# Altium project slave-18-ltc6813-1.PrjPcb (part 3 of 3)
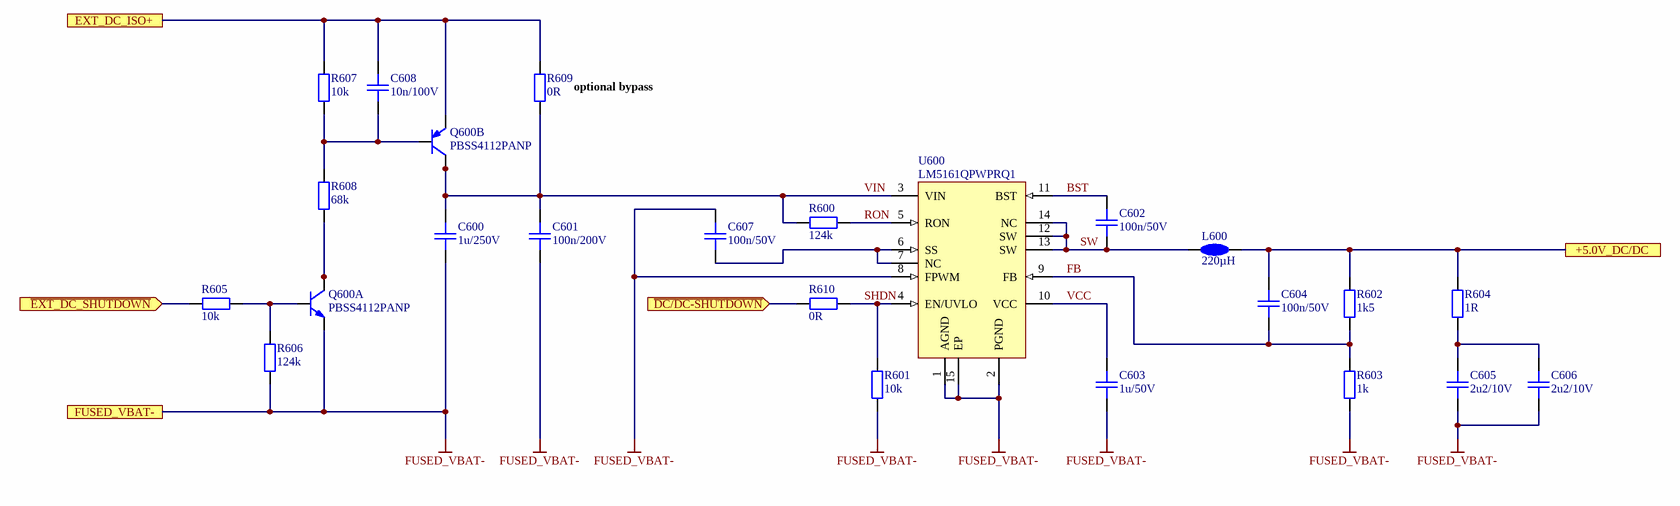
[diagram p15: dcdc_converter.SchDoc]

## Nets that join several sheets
+3.0V_VREF2: connectors (C401.2 C405.2 X400.17 X404.1), U_primary_LTC (C1402_1.2 IC1400_1.50 TP1402_1.1), U_primary_analog_in (9 pins)
+3.0V_VREF2: connectors (C400.2 C406.2 X401.17 X404.2), U_secondary_analog_in (9 pins), U_secondary_LTC (C1402_2.2 IC1400_2.50 TP1402_2.1)
+5.0V_VREG: connectors (C402.2 C404.2 X402.9 X404.3), feedback (D1100.2), U_primary_LTC (16 pins), U_primary_dcdc_converter (C604_1.2 L600_1.2 R602_1.1 R604_1.1), U_primary_digital_io (13 pins), U_primary_eeprom_temp_sens (6 pins), U_primary_analog_in (15 pins)
+5.0V_VREG: connectors (C403.2 C407.2 X403.9 X404.4), feedback (D1100.1), U_secondary_digital_io (13 pins), U_secondary_eeprom_temp_sens (6 pins), U_secondary_analog_in (15 pins), U_secondary_dcdc_converter (C604_2.2 L600_2.2 R602_2.1 R604_2.1), U_secondary_LTC (16 pins)
FUSED_VBAT+: cell_fuses (F300.2), U_primary_LTC (D1400_1.1), U_secondary_LTC (D1400_2.1)
FUSED_VBAT-: cell_fuses (F320.2), U_primary_input_filter (18 pins), U_secondary_input_filter (18 pins), ext_supply (6 pins), connectors (14 pins), feedback (C1100.1 R1118.2), U_primary_LTC (14 pins), U_secondary_digital_io (C700_1.1 C701_1.1 U700_1.2 U700_1.8), U_secondary_eeprom_temp_sens (5 pins), U_secondary_analog_in (25 pins), bat_connectors (16 pins), U_primary_dcdc_converter (14 pins), U_secondary_dcdc_converter (14 pins), U_secondary_LTC (14 pins), U_primary_digital_io (C700_2.1 C701_2.1 U700_2.2 U700_2.8), U_primary_eeprom_temp_sens (5 pins), U_primary_analog_in (25 pins)
VBAT+: cell_fuses (F300.1 SJ300.1), bat_connectors (X200.11)
VBAT-: cell_fuses (F320.1 SJ301.2), bat_connectors (X200.1)
CELL_0+: cell_fuses (F318.1), bat_connectors (X200.2)
CELL_0-: cell_fuses (F319.1 SJ301.1), bat_connectors (X200.13)
CELL_1+: cell_fuses (F317.1), bat_connectors (X200.14)
CELL_2+: cell_fuses (F316.1), bat_connectors (X200.3)
CELL_3+: cell_fuses (F315.1), bat_connectors (X200.15)
CELL_4+: cell_fuses (F314.1), bat_connectors (X200.4)
CELL_5+: cell_fuses (F313.1), bat_connectors (X200.16)
CELL_6+: cell_fuses (F312.1), bat_connectors (X200.5)
CELL_7+: cell_fuses (F311.1), bat_connectors (X200.17)
CELL_8+: cell_fuses (F310.1), bat_connectors (X200.6)
CELL_9+: cell_fuses (F309.1), bat_connectors (X200.18)
CELL_10+: cell_fuses (F308.1), bat_connectors (X200.7)
CELL_11+: cell_fuses (F307.1), bat_connectors (X200.19)
CELL_12+: cell_fuses (F306.1), bat_connectors (X200.8)
CELL_13+: cell_fuses (F305.1), bat_connectors (X200.20)
CELL_14+: cell_fuses (F304.1), bat_connectors (X200.9)
CELL_15+: cell_fuses (F303.1), bat_connectors (X200.21)
CELL_16+: cell_fuses (F302.1), bat_connectors (X200.10)
CELL_17+: cell_fuses (F301.1 SJ300.2), bat_connectors (X200.22)
CELL_FEEDBACK.CELL0_FEEDBACK+: feedback (R1105.1), passive_balancing (R1505.2 R1511.2 T1505.3)
CELL_FEEDBACK.CELL1_FEEDBACK+: feedback (R1104.1), passive_balancing (R1504.2 R1510.2 T1504.3)
CELL_FEEDBACK.CELL2_FEEDBACK+: feedback (R1103.1), passive_balancing (R1503.2 R1509.2 T1503.3)
CELL_FEEDBACK.CELL3_FEEDBACK+: feedback (R1102.1), passive_balancing (R1502.2 R1508.2 T1502.3)
CELL_FEEDBACK.CELL4_FEEDBACK+: feedback (R1101.1), passive_balancing (R1501.2 R1507.2 T1501.3)
CELL_FEEDBACK.CELL5_FEEDBACK+: feedback (R1100.1), passive_balancing (R1500.2 R1506.2 T1500.3)
CELL_FEEDBACK.CELL6_FEEDBACK+: feedback (R1111.1), passive_balancing (R1523.2 R1529.2 T1511.3)
CELL_FEEDBACK.CELL7_FEEDBACK+: feedback (R1110.1), passive_balancing (R1522.2 R1528.2 T1510.3)
CELL_FEEDBACK.CELL8_FEEDBACK+: feedback (R1109.1), passive_balancing (R1521.2 R1527.2 T1509.3)
CELL_FEEDBACK.CELL9_FEEDBACK+: feedback (R1108.1), passive_balancing (R1520.2 R1526.2 T1508.3)
CELL_FEEDBACK.CELL10_FEEDBACK+: feedback (R1107.1), passive_balancing (R1519.2 R1525.2 T1507.3)
CELL_FEEDBACK.CELL11_FEEDBACK+: feedback (R1106.1), passive_balancing (R1518.2 R1524.2 T1506.3)
CELL_FEEDBACK.CELL12_FEEDBACK+: feedback (R1117.1), passive_balancing (R1541.2 R1547.2 T1517.3)
CELL_FEEDBACK.CELL13_FEEDBACK+: feedback (R1116.1), passive_balancing (R1540.2 R1546.2 T1516.3)
CELL_FEEDBACK.CELL14_FEEDBACK+: feedback (R1115.1), passive_balancing (R1539.2 R1545.2 T1515.3)
CELL_FEEDBACK.CELL15_FEEDBACK+: feedback (R1114.1), passive_balancing (R1538.2 R1544.2 T1514.3)
CELL_FEEDBACK.CELL16_FEEDBACK+: feedback (R1113.1), passive_balancing (R1537.2 R1543.2 T1513.3)
CELL_FEEDBACK.CELL17_FEEDBACK+: feedback (R1112.1), passive_balancing (R1536.2 R1542.2 T1512.3)
EXT_DC_IN+: ext_supply (F900.1), ext_supply_con (X1000.1 X1000.3 X1001.1 X1002.1)
EXT_DC_IN-: ext_supply (10 pins), ext_supply_con (X1000.2 X1000.4 X1001.2 X1002.2)
EXT_DC_ISO+: ext_supply (5 pins), U_primary_LTC (D1400_1.2 D1401_1.1 R1401_1.1), U_primary_dcdc_converter (C608_1.1 Q600_1.4 R607_1.2 R609_1.2), U_secondary_dcdc_converter (C608_2.1 Q600_2.4 R607_2.2 R609_2.2), U_secondary_LTC (D1400_2.2 D1401_2.1 R1401_2.1)
FUSED_CELL.CELL_0+: cell_fuses (F318.2), U_primary_input_filter (R1305_1.1), U_secondary_input_filter (R1305_2.1), feedback (U1104.2), passive_balancing (R1504.1 R1510.1 T1505.2)
FUSED_CELL.CELL_0-: cell_fuses (F319.2), U_primary_input_filter (R1306_1.1), U_secondary_input_filter (R1306_2.1), feedback (U1105.2), passive_balancing (R1505.1 R1511.1)
FUSED_CELL.CELL_1+: cell_fuses (F317.2), U_primary_input_filter (R1304_1.1), U_secondary_input_filter (R1304_2.1), feedback (U1103.2), passive_balancing (R1503.1 R1509.1 T1504.2)
FUSED_CELL.CELL_2+: cell_fuses (F316.2), U_primary_input_filter (R1303_1.1), U_secondary_input_filter (R1303_2.1), feedback (U1102.2), passive_balancing (R1502.1 R1508.1 T1503.2)
FUSED_CELL.CELL_3+: cell_fuses (F315.2), U_primary_input_filter (R1302_1.1), U_secondary_input_filter (R1302_2.1), feedback (U1101.2), passive_balancing (R1501.1 R1507.1 T1502.2)
FUSED_CELL.CELL_4+: cell_fuses (F314.2), U_primary_input_filter (R1301_1.1), U_secondary_input_filter (R1301_2.1), feedback (U1100.2), passive_balancing (R1500.1 R1506.1 T1501.2)
FUSED_CELL.CELL_5+: cell_fuses (F313.2), U_primary_input_filter (R1300_1.1), U_secondary_input_filter (R1300_2.1), feedback (U1111.2), passive_balancing (R1523.1 R1529.1 T1500.2)
FUSED_CELL.CELL_6+: cell_fuses (F312.2), U_primary_input_filter (R1312_1.1), U_secondary_input_filter (R1312_2.1), feedback (U1110.2), passive_balancing (R1522.1 R1528.1 T1511.2)
FUSED_CELL.CELL_7+: cell_fuses (F311.2), U_primary_input_filter (R1311_1.1), U_secondary_input_filter (R1311_2.1), feedback (U1109.2), passive_balancing (R1521.1 R1527.1 T1510.2)
FUSED_CELL.CELL_8+: cell_fuses (F310.2), U_primary_input_filter (R1310_1.1), U_secondary_input_filter (R1310_2.1), feedback (U1108.2), passive_balancing (R1520.1 R1526.1 T1509.2)
FUSED_CELL.CELL_9+: cell_fuses (F309.2), U_primary_input_filter (R1309_1.1), U_secondary_input_filter (R1309_2.1), feedback (U1107.2), passive_balancing (R1519.1 R1525.1 T1508.2)
FUSED_CELL.CELL_10+: cell_fuses (F308.2), U_primary_input_filter (R1308_1.1), U_secondary_input_filter (R1308_2.1), feedback (U1106.2), passive_balancing (R1518.1 R1524.1 T1507.2)
FUSED_CELL.CELL_11+: cell_fuses (F307.2), U_primary_input_filter (R1307_1.1), U_secondary_input_filter (R1307_2.1), feedback (U1117.2), passive_balancing (R1541.1 R1547.1 T1506.2)
FUSED_CELL.CELL_12+: cell_fuses (F306.2), U_primary_input_filter (R1318_1.1), U_secondary_input_filter (R1318_2.1), feedback (U1116.2), passive_balancing (R1540.1 R1546.1 T1517.2)
FUSED_CELL.CELL_13+: cell_fuses (F305.2), U_primary_input_filter (R1317_1.1), U_secondary_input_filter (R1317_2.1), feedback (U1115.2), passive_balancing (R1539.1 R1545.1 T1516.2)
FUSED_CELL.CELL_14+: cell_fuses (F304.2), U_primary_input_filter (R1316_1.1), U_secondary_input_filter (R1316_2.1), feedback (U1114.2), passive_balancing (R1538.1 R1544.1 T1515.2)
FUSED_CELL.CELL_15+: cell_fuses (F303.2), U_primary_input_filter (R1315_1.1), U_secondary_input_filter (R1315_2.1), feedback (U1113.2), passive_balancing (R1537.1 R1543.1 T1514.2)
FUSED_CELL.CELL_16+: cell_fuses (F302.2), U_primary_input_filter (R1314_1.1), U_secondary_input_filter (R1314_2.1), feedback (U1112.2), passive_balancing (R1536.1 R1542.1 T1513.2)
FUSED_CELL.CELL_17+: cell_fuses (F301.2), U_primary_input_filter (R1313_1.1), U_secondary_input_filter (R1313_2.1), passive_balancing (T1512.2)
GLOBAL-BAL-FB: feedback (20 pins), U_primary_LTC (R1413_1.1), U_secondary_LTC (R1413_2.1)
PRIMARY-ANALOG-IN_0: connectors (X400.1), U_primary_analog_in (IC104_2.4)
PRIMARY-ANALOG-IN_1: connectors (X400.2), U_primary_analog_in (IC104_2.5)
PRIMARY-ANALOG-IN_2: connectors (X400.3), U_primary_analog_in (IC104_2.6)
PRIMARY-ANALOG-IN_3: connectors (X400.4), U_primary_analog_in (IC104_2.7)
PRIMARY-ANALOG-IN_4: connectors (X400.5), U_primary_analog_in (IC104_2.12)
PRIMARY-ANALOG-IN_5: connectors (X400.6), U_primary_analog_in (IC104_2.11)
PRIMARY-ANALOG-IN_6: connectors (X400.7), U_primary_analog_in (IC104_2.10)
PRIMARY-ANALOG-IN_7: connectors (X400.8), U_primary_analog_in (IC104_2.9)
PRIMARY-ANALOG-IN_8: connectors (X400.9), U_primary_analog_in (IC101_2.4)
PRIMARY-ANALOG-IN_9: connectors (X400.10), U_primary_analog_in (IC101_2.5)
PRIMARY-ANALOG-IN_10: connectors (X400.11), U_primary_analog_in (IC101_2.6)
PRIMARY-ANALOG-IN_11: connectors (X400.12), U_primary_analog_in (IC101_2.7)
PRIMARY-ANALOG-IN_12: connectors (X400.13), U_primary_analog_in (IC101_2.12)
PRIMARY-ANALOG-IN_13: connectors (X400.14), U_primary_analog_in (IC101_2.11)
PRIMARY-ANALOG-IN_14: connectors (X400.15), U_primary_analog_in (IC101_2.10)
PRIMARY-ANALOG-IN_15: connectors (X400.16), U_primary_analog_in (IC101_2.9)
PRIMARY-C0: U_primary_input_filter (C1311_1.2 R1306_1.2 Z1305_1.2), U_primary_LTC (IC1400_1.38)
PRIMARY-C1: U_primary_input_filter (6 pins), U_primary_LTC (IC1400_1.36)
PRIMARY-C2: U_primary_input_filter (6 pins), U_primary_LTC (IC1400_1.34)
PRIMARY-C3: U_primary_input_filter (6 pins), U_primary_LTC (IC1400_1.32)
PRIMARY-C4: U_primary_input_filter (6 pins), U_primary_LTC (IC1400_1.30)
PRIMARY-C5: U_primary_input_filter (6 pins), U_primary_LTC (IC1400_1.28)
PRIMARY-C6: U_primary_input_filter (6 pins), U_primary_LTC (IC1400_1.26)
PRIMARY-C7: U_primary_input_filter (6 pins), U_primary_LTC (IC1400_1.24)
PRIMARY-C8: U_primary_input_filter (6 pins), U_primary_LTC (IC1400_1.22)
PRIMARY-C9: U_primary_input_filter (6 pins), U_primary_LTC (IC1400_1.20)
PRIMARY-C10: U_primary_input_filter (6 pins), U_primary_LTC (IC1400_1.18)
PRIMARY-C11: U_primary_input_filter (6 pins), U_primary_LTC (IC1400_1.16)
PRIMARY-C12: U_primary_input_filter (6 pins), U_primary_LTC (IC1400_1.14)
PRIMARY-C13: U_primary_input_filter (6 pins), U_primary_LTC (IC1400_1.12)
PRIMARY-C14: U_primary_input_filter (6 pins), U_primary_LTC (IC1400_1.10)
PRIMARY-C15: U_primary_input_filter (6 pins), U_primary_LTC (IC1400_1.8)
PRIMARY-C16: U_primary_input_filter (6 pins), U_primary_LTC (IC1400_1.6)
PRIMARY-C17: U_primary_input_filter (6 pins), U_primary_LTC (IC1400_1.4)
PRIMARY-C18: U_primary_input_filter (C1324_1.1 C1330_1.1 R1313_1.2 Z1312_1.1), U_primary_LTC (IC1400_1.2)
PRIMARY-DIGITAL-IO_0: connectors (X402.1), U_primary_digital_io (R700_2.1 U700_2.4)
PRIMARY-DIGITAL-IO_1: connectors (X402.2), U_primary_digital_io (R701_2.1 U700_2.5)
PRIMARY-DIGITAL-IO_2: connectors (X402.3), U_primary_digital_io (R702_2.1 U700_2.6)
PRIMARY-DIGITAL-IO_3: connectors (X402.4), U_primary_digital_io (R703_2.1 U700_2.7)
PRIMARY-DIGITAL-IO_4: connectors (X402.5), U_primary_digital_io (R704_2.1 U700_2.9)
PRIMARY-DIGITAL-IO_5: connectors (X402.6), U_primary_digital_io (R705_2.1 U700_2.10)
PRIMARY-DIGITAL-IO_6: connectors (X402.7), U_primary_digital_io (R706_2.1 U700_2.11)
PRIMARY-DIGITAL-IO_7: connectors (X402.8), U_primary_digital_io (R707_2.1 U700_2.12)
PRIMARY-GPIO1-OPT: connectors (X404.5), U_primary_LTC (R1408_1.1 R1425_1.1)
PRIMARY-GPIO2-OPT: connectors (X404.7), U_primary_LTC (R1410_1.1 R1426_1.1)
PRIMARY-GPIO3-OPT: connectors (X404.9), U_primary_LTC (R1412_1.1 R1427_1.1)
PRIMARY-GPIO4-OPT: connectors (X404.11), U_primary_LTC (R1414_1.1)
PRIMARY-GPIO5-OPT: connectors (X404.13), U_primary_LTC (R1416_1.1)
PRIMARY-GPIO6: connectors (X405.1), U_primary_LTC (IC1400_1.44 R1421_1.1)
PRIMARY-GPIO7: connectors (X405.3), U_primary_LTC (IC1400_1.45 R1422_1.1)
PRIMARY-GPIO8: connectors (X405.5), U_primary_LTC (IC1400_1.46 R1423_1.1)
PRIMARY-GPIO9: connectors (X405.7), U_primary_LTC (IC1400_1.47 R1424_1.1)
PRIMARY-IN+: U_primary_LTC (TP1405_1.1 TR1400_1.4), daisy_chain_connectors (X500.1)
PRIMARY-IN-: U_primary_LTC (TP1404_1.1 TR1400_1.6), daisy_chain_connectors (X500.2)
PRIMARY-LTC-DRIVE: U_primary_LTC (IC1400_1.49), U_primary_dcdc_converter (R605_1.1 R610_1.2)
PRIMARY-MUX-DATA_TEMP: U_primary_LTC (R1409_1.1), U_primary_analog_in (C106_2.2 R108_2.2)
PRIMARY-MUX-DATA_USER: U_primary_LTC (R1411_1.1), U_primary_analog_in (C107_2.2 R109_2.2)
PRIMARY-OUT+: U_primary_LTC (TP1406_1.1 TR1400_1.1), daisy_chain_connectors (X501.1)
PRIMARY-OUT-: U_primary_LTC (TP1407_1.1 TR1400_1.3), daisy_chain_connectors (X501.2)
PRIMARY-S1: passive_balancing (R1517.2), U_primary_LTC (IC1400_1.37)
PRIMARY-S2: passive_balancing (R1516.2), U_primary_LTC (IC1400_1.35)
PRIMARY-S3: passive_balancing (R1515.2), U_primary_LTC (IC1400_1.33)
PRIMARY-S4: passive_balancing (R1514.2), U_primary_LTC (IC1400_1.31)
PRIMARY-S5: passive_balancing (R1513.2), U_primary_LTC (IC1400_1.29)
PRIMARY-S6: passive_balancing (R1512.2), U_primary_LTC (IC1400_1.27)
PRIMARY-S7: passive_balancing (R1535.2), U_primary_LTC (IC1400_1.25)
PRIMARY-S8: passive_balancing (R1534.2), U_primary_LTC (IC1400_1.23)
PRIMARY-S9: passive_balancing (R1533.2), U_primary_LTC (IC1400_1.21)
PRIMARY-S10: passive_balancing (R1532.2), U_primary_LTC (IC1400_1.19)
PRIMARY-S11: passive_balancing (R1531.2), U_primary_LTC (IC1400_1.17)
PRIMARY-S12: passive_balancing (R1530.2), U_primary_LTC (IC1400_1.15)
PRIMARY-S13: passive_balancing (R1553.2), U_primary_LTC (IC1400_1.13)
PRIMARY-S14: passive_balancing (R1552.2), U_primary_LTC (IC1400_1.11)
PRIMARY-S15: passive_balancing (R1551.2), U_primary_LTC (IC1400_1.9)
PRIMARY-S16: passive_balancing (R1550.2), U_primary_LTC (IC1400_1.7)
PRIMARY-S17: passive_balancing (R1549.2), U_primary_LTC (IC1400_1.5)
PRIMARY-S18: passive_balancing (R1548.2), U_primary_LTC (IC1400_1.3)
PRIMARY-SCL: U_primary_LTC (R1417_1.1 R1420_1.1 TP1409_1.1), U_primary_digital_io (U700_2.14), U_primary_eeprom_temp_sens (IC800_2.4 IC801_2.6), U_primary_analog_in (IC100_2.1 IC101_2.1 IC104_2.1)
PRIMARY-SDA: U_primary_LTC (R1415_1.1 R1419_1.1 TP1408_1.1), U_primary_digital_io (U700_2.15), U_primary_eeprom_temp_sens (IC800_2.5 IC801_2.5), U_primary_analog_in (IC100_2.3 IC101_2.3 IC104_2.3)
PRIMARY-T-SENSOR_0: bat_connectors (X201.1), U_primary_analog_in (R107_2.1 R112_2.2)
PRIMARY-T-SENSOR_1: bat_connectors (X201.2), U_primary_analog_in (R106_2.1 R113_2.2)
PRIMARY-T-SENSOR_2: bat_connectors (X201.3), U_primary_analog_in (R105_2.1 R114_2.2)
PRIMARY-T-SENSOR_3: bat_connectors (X201.4), U_primary_analog_in (R104_2.1 R115_2.2)
PRIMARY-T-SENSOR_4: bat_connectors (X201.5), U_primary_analog_in (R103_2.1 R116_2.2)
PRIMARY-T-SENSOR_5: bat_connectors (X201.6), U_primary_analog_in (R102_2.1 R117_2.2)
PRIMARY-T-SENSOR_6: bat_connectors (X201.7), U_primary_analog_in (R101_2.1 R118_2.2)
PRIMARY-T-SENSOR_7: bat_connectors (X201.8), U_primary_analog_in (R100_2.1 R119_2.2)
PRIMARY-TEMP-ALERT: connectors (X404.17), U_primary_eeprom_temp_sens (IC800_2.3 R800_2.1)
PRIMARY-WDT: connectors (X404.15), U_primary_LTC (IC1400_1.56 R1404_1.1)
SECONDARY-ANALOG-IN_0: connectors (X401.1), U_secondary_analog_in (IC104_1.4)
SECONDARY-ANALOG-IN_1: connectors (X401.2), U_secondary_analog_in (IC104_1.5)
SECONDARY-ANALOG-IN_2: connectors (X401.3), U_secondary_analog_in (IC104_1.6)
SECONDARY-ANALOG-IN_3: connectors (X401.4), U_secondary_analog_in (IC104_1.7)
SECONDARY-ANALOG-IN_4: connectors (X401.5), U_secondary_analog_in (IC104_1.12)
SECONDARY-ANALOG-IN_5: connectors (X401.6), U_secondary_analog_in (IC104_1.11)
SECONDARY-ANALOG-IN_6: connectors (X401.7), U_secondary_analog_in (IC104_1.10)
SECONDARY-ANALOG-IN_7: connectors (X401.8), U_secondary_analog_in (IC104_1.9)
SECONDARY-ANALOG-IN_8: connectors (X401.9), U_secondary_analog_in (IC101_1.4)
SECONDARY-ANALOG-IN_9: connectors (X401.10), U_secondary_analog_in (IC101_1.5)
SECONDARY-ANALOG-IN_10: connectors (X401.11), U_secondary_analog_in (IC101_1.6)
SECONDARY-ANALOG-IN_11: connectors (X401.12), U_secondary_analog_in (IC101_1.7)
SECONDARY-ANALOG-IN_12: connectors (X401.13), U_secondary_analog_in (IC101_1.12)
SECONDARY-ANALOG-IN_13: connectors (X401.14), U_secondary_analog_in (IC101_1.11)
SECONDARY-ANALOG-IN_14: connectors (X401.15), U_secondary_analog_in (IC101_1.10)
SECONDARY-ANALOG-IN_15: connectors (X401.16), U_secondary_analog_in (IC101_1.9)
SECONDARY-C0: U_secondary_input_filter (C1311_2.2 R1306_2.2 Z1305_2.2), U_secondary_LTC (IC1400_2.38)
SECONDARY-C1: U_secondary_input_filter (6 pins), U_secondary_LTC (IC1400_2.36)
SECONDARY-C2: U_secondary_input_filter (6 pins), U_secondary_LTC (IC1400_2.34)
SECONDARY-C3: U_secondary_input_filter (6 pins), U_secondary_LTC (IC1400_2.32)
SECONDARY-C4: U_secondary_input_filter (6 pins), U_secondary_LTC (IC1400_2.30)
SECONDARY-C5: U_secondary_input_filter (6 pins), U_secondary_LTC (IC1400_2.28)
SECONDARY-C6: U_secondary_input_filter (6 pins), U_secondary_LTC (IC1400_2.26)
SECONDARY-C7: U_secondary_input_filter (6 pins), U_secondary_LTC (IC1400_2.24)
SECONDARY-C8: U_secondary_input_filter (6 pins), U_secondary_LTC (IC1400_2.22)
SECONDARY-C9: U_secondary_input_filter (6 pins), U_secondary_LTC (IC1400_2.20)
SECONDARY-C10: U_secondary_input_filter (6 pins), U_secondary_LTC (IC1400_2.18)
SECONDARY-C11: U_secondary_input_filter (6 pins), U_secondary_LTC (IC1400_2.16)
SECONDARY-C12: U_secondary_input_filter (6 pins), U_secondary_LTC (IC1400_2.14)
SECONDARY-C13: U_secondary_input_filter (6 pins), U_secondary_LTC (IC1400_2.12)
SECONDARY-C14: U_secondary_input_filter (6 pins), U_secondary_LTC (IC1400_2.10)
SECONDARY-C15: U_secondary_input_filter (6 pins), U_secondary_LTC (IC1400_2.8)
SECONDARY-C16: U_secondary_input_filter (6 pins), U_secondary_LTC (IC1400_2.6)
SECONDARY-C17: U_secondary_input_filter (6 pins), U_secondary_LTC (IC1400_2.4)
SECONDARY-C18: U_secondary_input_filter (C1324_2.1 C1330_2.1 R1313_2.2 Z1312_2.1), U_secondary_LTC (IC1400_2.2)
SECONDARY-DIGITAL-IO_0: connectors (X403.1), U_secondary_digital_io (R700_1.1 U700_1.4)
SECONDARY-DIGITAL-IO_1: connectors (X403.2), U_secondary_digital_io (R701_1.1 U700_1.5)
SECONDARY-DIGITAL-IO_2: connectors (X403.3), U_secondary_digital_io (R702_1.1 U700_1.6)
SECONDARY-DIGITAL-IO_3: connectors (X403.4), U_secondary_digital_io (R703_1.1 U700_1.7)
SECONDARY-DIGITAL-IO_4: connectors (X403.5), U_secondary_digital_io (R704_1.1 U700_1.9)
SECONDARY-DIGITAL-IO_5: connectors (X403.6), U_secondary_digital_io (R705_1.1 U700_1.10)
SECONDARY-DIGITAL-IO_6: connectors (X403.7), U_secondary_digital_io (R706_1.1 U700_1.11)
SECONDARY-DIGITAL-IO_7: connectors (X403.8), U_secondary_digital_io (R707_1.1 U700_1.12)
SECONDARY-GPIO1-OPT: connectors (X404.6), U_secondary_LTC (R1408_2.1 R1425_2.1)
SECONDARY-GPIO2-OPT: connectors (X404.8), U_secondary_LTC (R1410_2.1 R1426_2.1)
SECONDARY-GPIO3-OPT: connectors (X404.10), U_secondary_LTC (R1412_2.1 R1427_2.1)
SECONDARY-GPIO4-OPT: connectors (X404.12), U_secondary_LTC (R1414_2.1)
SECONDARY-GPIO5-OPT: connectors (X404.14), U_secondary_LTC (R1416_2.1)
SECONDARY-GPIO6: connectors (X405.2), U_secondary_LTC (IC1400_2.44 R1421_2.1)
SECONDARY-GPIO7: connectors (X405.4), U_secondary_LTC (IC1400_2.45 R1422_2.1)
SECONDARY-GPIO8: connectors (X405.6), U_secondary_LTC (IC1400_2.46 R1423_2.1)
SECONDARY-GPIO9: connectors (X405.8), U_secondary_LTC (IC1400_2.47 R1424_2.1)
SECONDARY-IN+: daisy_chain_connectors (X502.1), U_secondary_LTC (TP1405_2.1 TR1400_2.4)
SECONDARY-IN-: daisy_chain_connectors (X502.2), U_secondary_LTC (TP1404_2.1 TR1400_2.6)
SECONDARY-LTC-DRIVE: U_secondary_dcdc_converter (R605_2.1 R610_2.2), U_secondary_LTC (IC1400_2.49)
SECONDARY-MUX-DATA_TEMP: U_secondary_analog_in (C106_1.2 R108_1.2), U_secondary_LTC (R1409_2.1)
SECONDARY-MUX-DATA_USER: U_secondary_analog_in (C107_1.2 R109_1.2), U_secondary_LTC (R1411_2.1)
SECONDARY-OUT+: daisy_chain_connectors (X503.1), U_secondary_LTC (TP1406_2.1 TR1400_2.1)
SECONDARY-OUT-: daisy_chain_connectors (X503.2), U_secondary_LTC (TP1407_2.1 TR1400_2.3)
SECONDARY-SCL: U_secondary_digital_io (U700_1.14), U_secondary_eeprom_temp_sens (IC800_1.4 IC801_1.6), U_secondary_analog_in (IC100_1.1 IC101_1.1 IC104_1.1), U_secondary_LTC (R1417_2.1 R1420_2.1 TP1409_2.1)
SECONDARY-SDA: U_secondary_digital_io (U700_1.15), U_secondary_eeprom_temp_sens (IC800_1.5 IC801_1.5), U_secondary_analog_in (IC100_1.3 IC101_1.3 IC104_1.3), U_secondary_LTC (R1415_2.1 R1419_2.1 TP1408_2.1)
SECONDARY-T-SENSOR_0: U_secondary_analog_in (R107_1.1 R112_1.2), bat_connectors (X202.1)
SECONDARY-T-SENSOR_1: U_secondary_analog_in (R106_1.1 R113_1.2), bat_connectors (X202.2)
SECONDARY-T-SENSOR_2: U_secondary_analog_in (R105_1.1 R114_1.2), bat_connectors (X202.3)
SECONDARY-T-SENSOR_3: U_secondary_analog_in (R104_1.1 R115_1.2), bat_connectors (X202.4)
SECONDARY-T-SENSOR_4: U_secondary_analog_in (R103_1.1 R116_1.2), bat_connectors (X202.5)
SECONDARY-T-SENSOR_5: U_secondary_analog_in (R102_1.1 R117_1.2), bat_connectors (X202.6)
SECONDARY-T-SENSOR_6: U_secondary_analog_in (R101_1.1 R118_1.2), bat_connectors (X202.7)
SECONDARY-T-SENSOR_7: U_secondary_analog_in (R100_1.1 R119_1.2), bat_connectors (X202.8)
SECONDARY-TEMP-ALERT: connectors (X404.18), U_secondary_eeprom_temp_sens (IC800_1.3 R800_1.1)
SECONDARY-WDT: connectors (X404.16), U_secondary_LTC (IC1400_2.56 R1404_2.1)

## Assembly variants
default: not fitted C1306_1 C1306_2 C1307_1 C1307_2 C1308_1 C1308_2 C1309_1 C1309_2 C1310_1 C1310_2 C1311_1 C1311_2 C1318_1 C1318_2 C1319_1 C1319_2 C1320_1 C1320_2 C1321_1 C1321_2 C1322_1 C1322_2 C1323_1 C1323_2 C1330_1 C1330_2 C1331_1 C1331_2 C1332_1 C1332_2 C1333_1 C1333_2 C1334_1 C1334_2 C1335_1 C1335_2 R110_1 R110_2 R111_1 R111_2 R609_1 R609_2 R801_1 R801_2 R902 R1406_1 R1406_2 R1408_1 R1408_2 R1410_1 R1410_2 R1412_1 R1412_2 R1414_1 R1414_2 R1416_1 R1416_2 R1425_1 R1425_2 R1426_1 R1426_2 R1427_1 R1427_2 SJ300 SJ301 X900 X1000
automotive: not fitted C1306_1 C1306_2 C1307_1 C1307_2 C1308_1 C1308_2 C1309_1 C1309_2 C1310_1 C1310_2 C1311_1 C1311_2 C1318_1 C1318_2 C1319_1 C1319_2 C1320_1 C1320_2 C1321_1 C1321_2 C1322_1 C1322_2 C1323_1 C1323_2 C1330_1 C1330_2 C1331_1 C1331_2 C1332_1 C1332_2 C1333_1 C1333_2 C1334_1 C1334_2 C1335_1 C1335_2 R110_1 R110_2 R111_1 R111_2 R609_1 R609_2 R801_1 R801_2 R902 R1406_1 R1406_2 R1408_1 R1408_2 R1410_1 R1410_2 R1412_1 R1412_2 R1414_1 R1414_2 R1416_1 R1416_2 R1425_1 R1425_2 R1426_1 R1426_2 R1427_1 R1427_2 SJ300 SJ301 X900 X1000; alternate parts U1100 -> TLX9291A, U1101 -> TLX9291A, U1117 -> TLX9291A, U1116 -> TLX9291A, U1115 -> TLX9291A, U1114 -> TLX9291A, U1113 -> TLX9291A, U1112 -> TLX9291A, U1111 -> TLX9291A, U1110 -> TLX9291A, U1109 -> TLX9291A, U1108 -> TLX9291A, U1107 -> TLX9291A, U1106 -> TLX9291A, U1105 -> TLX9291A, U1104 -> TLX9291A, U1103 -> TLX9291A, U1102 -> TLX9291A
automotive_single-AFE: not fitted C1306_1 C1306_2 C1307_1 C1307_2 C1308_1 C1308_2 C1309_1 C1309_2 C1310_1 C1310_2 C1311_1 C1311_2 C1318_1 C1318_2 C1319_1 C1319_2 C1320_1 C1320_2 C1321_1 C1321_2 C1322_1 C1322_2 C1323_1 C1323_2 C1330_1 C1330_2 C1331_1 C1331_2 C1332_1 C1332_2 C1333_1 C1333_2 C1334_1 C1334_2 C1335_1 C1335_2 IC1400_2 R110_1 R110_2 R111_1 R111_2 R609_1 R609_2 R801_1 R801_2 R902 R1406_1 R1406_2 R1408_1 R1408_2 R1410_1 R1410_2 R1412_1 R1412_2 R1414_1 R1414_2 R1416_1 R1416_2 R1425_1 R1425_2 R1426_1 R1426_2 R1427_1 R1427_2 SJ300 SJ301 X400 X401 X402 X403 X404 X405 X900 X1000; alternate parts U1100 -> TLX9291A, U1101 -> TLX9291A, U1117 -> TLX9291A, U1116 -> TLX9291A, U1115 -> TLX9291A, U1114 -> TLX9291A, U1113 -> TLX9291A, U1112 -> TLX9291A, U1111 -> TLX9291A, U1110 -> TLX9291A, U1109 -> TLX9291A, U1108 -> TLX9291A, U1107 -> TLX9291A, U1106 -> TLX9291A, U1105 -> TLX9291A, U1104 -> TLX9291A, U1103 -> TLX9291A, U1102 -> TLX9291A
